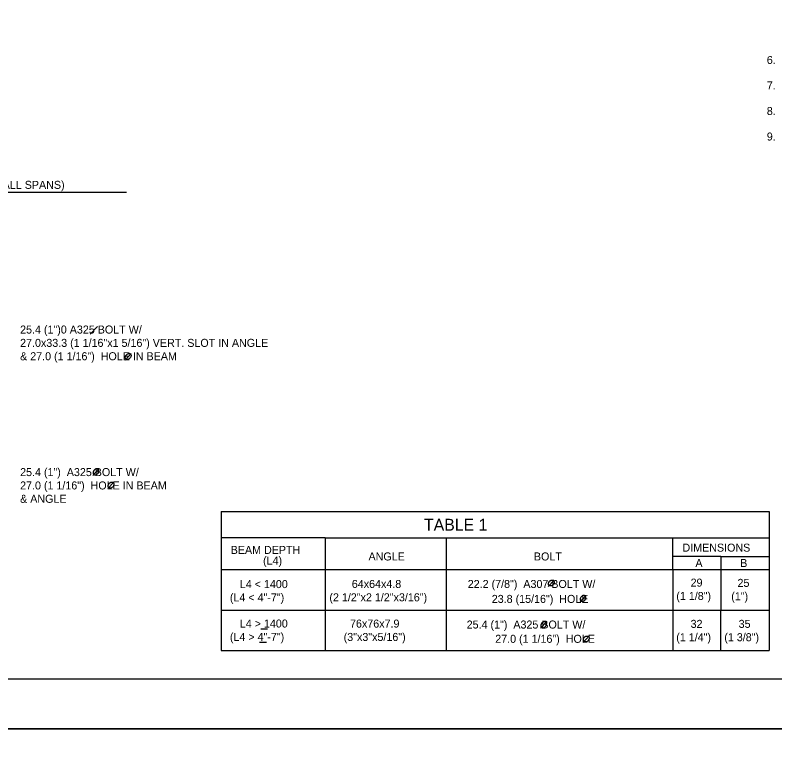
# Model space of a CAD drawing. Extents: x -13 to 81, y -176 to 0.
# Drawn here: x 47.85 to 59.23, y -22.38 to -11.31 of the extents above; entities that cross this region are included whole.
import ezdxf

# ---------------------------------------------------------------- set-up
doc = ezdxf.new("R2010")
doc.units = 0
for name, color, linetype in [('Level 1', 7, 'Continuous'), ('Level 3', 7, 'Continuous'), ('Level 4', 7, 'Continuous'), ('Level 5', 7, 'Continuous'), ('Level 63', 7, 'Continuous'), ('Level 8', 7, 'Continuous')]:
    doc.layers.add(name, color=color, linetype=linetype)

msp = doc.modelspace()

# ---------------------------------------------------------------- linework, layer by layer
at = {"layer": 'Level 1'}
msp.add_lwpolyline([(35.75, -21.25), (67.25, -21.25), (67.25, -0.75), (35.75, -0.75)], close=True, dxfattribs=at)
at = {"layer": 'Level 3'}
for p, q in [((49.087, -15.973), (48.974, -16.086)), ((51.532, -20.504), (51.635, -20.504)), ((51.512, -20.702), (51.616, -20.702))]:
    msp.add_line(p, q, dxfattribs=at)
at = {"layer": 'Level 4'}
for p, q in [((49.499, -16.475), (49.588, -16.377)), ((49.017, -18.203), (49.107, -18.104)), ((49.241, -18.402), (49.331, -18.304)), ((55.84, -19.869), (55.929, -19.771)), ((56.315, -20.1), (56.404, -20.002)), ((55.725, -20.494), (55.814, -20.396)), ((56.363, -20.707), (56.452, -20.609))]:
    msp.add_line(p, q, dxfattribs=at)
for points in [[(49.579, -16.386), (49.572, -16.381), (49.565, -16.379), (49.556, -16.378), (49.551, -16.378), (49.543, -16.38), (49.535, -16.384), (49.529, -16.387), (49.519, -16.395), (49.51, -16.406), (49.505, -16.416), (49.502, -16.425), (49.501, -16.434), (49.502, -16.441), (49.506, -16.452), (49.51, -16.457), (49.517, -16.463), (49.529, -16.466), (49.542, -16.466), (49.559, -16.458), (49.571, -16.447), (49.58, -16.435), (49.586, -16.421), (49.588, -16.407), (49.586, -16.397), (49.579, -16.386)], [(49.097, -18.114), (49.09, -18.109), (49.083, -18.107), (49.075, -18.106), (49.069, -18.106), (49.061, -18.108), (49.053, -18.112), (49.048, -18.115), (49.037, -18.123), (49.029, -18.134), (49.024, -18.144), (49.021, -18.153), (49.02, -18.162), (49.021, -18.169), (49.024, -18.18), (49.028, -18.185), (49.036, -18.191), (49.047, -18.194), (49.061, -18.194), (49.077, -18.186), (49.09, -18.175), (49.099, -18.163), (49.105, -18.149), (49.107, -18.135), (49.104, -18.125), (49.098, -18.114)], [(49.322, -18.313), (49.314, -18.308), (49.307, -18.306), (49.299, -18.305), (49.294, -18.305), (49.285, -18.307), (49.277, -18.311), (49.272, -18.314), (49.261, -18.323), (49.253, -18.333), (49.248, -18.343), (49.245, -18.353), (49.244, -18.361), (49.245, -18.369), (49.249, -18.379), (49.252, -18.385), (49.26, -18.391), (49.272, -18.393), (49.285, -18.393), (49.302, -18.385), (49.314, -18.375), (49.323, -18.362), (49.329, -18.349), (49.331, -18.334), (49.328, -18.325), (49.322, -18.313)], [(55.92, -19.78), (55.913, -19.775), (55.906, -19.773), (55.897, -19.772), (55.892, -19.772), (55.884, -19.774), (55.876, -19.778), (55.87, -19.781), (55.86, -19.79), (55.851, -19.8), (55.846, -19.81), (55.843, -19.82), (55.842, -19.828), (55.843, -19.836), (55.847, -19.846), (55.851, -19.852), (55.858, -19.858), (55.87, -19.86), (55.883, -19.86), (55.9, -19.852), (55.912, -19.842), (55.921, -19.829), (55.927, -19.816), (55.929, -19.801), (55.927, -19.792), (55.92, -19.78)], [(56.395, -20.011), (56.388, -20.006), (56.381, -20.004), (56.372, -20.003), (56.367, -20.003), (56.359, -20.005), (56.351, -20.009), (56.345, -20.012), (56.335, -20.02), (56.326, -20.031), (56.321, -20.041), (56.319, -20.05), (56.318, -20.059), (56.319, -20.066), (56.322, -20.077), (56.326, -20.082), (56.334, -20.088), (56.345, -20.091), (56.358, -20.091), (56.375, -20.083), (56.387, -20.073), (56.396, -20.06), (56.402, -20.047), (56.404, -20.032), (56.402, -20.023), (56.396, -20.011)], [(55.805, -20.406), (55.798, -20.401), (55.791, -20.399), (55.782, -20.398), (55.777, -20.398), (55.769, -20.4), (55.761, -20.403), (55.755, -20.406), (55.745, -20.415), (55.736, -20.426), (55.731, -20.436), (55.728, -20.445), (55.728, -20.454), (55.728, -20.461), (55.732, -20.472), (55.736, -20.477), (55.744, -20.483), (55.755, -20.486), (55.768, -20.485), (55.785, -20.478), (55.797, -20.467), (55.806, -20.454), (55.812, -20.441), (55.814, -20.427), (55.812, -20.417), (55.806, -20.406)], [(56.443, -20.619), (56.436, -20.613), (56.429, -20.611), (56.42, -20.611), (56.415, -20.611), (56.407, -20.613), (56.399, -20.616), (56.393, -20.619), (56.383, -20.628), (56.374, -20.639), (56.369, -20.649), (56.366, -20.658), (56.365, -20.666), (56.366, -20.674), (56.37, -20.684), (56.374, -20.69), (56.381, -20.696), (56.393, -20.698), (56.406, -20.698), (56.423, -20.69), (56.435, -20.68), (56.444, -20.667), (56.45, -20.654), (56.452, -20.639), (56.45, -20.63), (56.443, -20.619)]]:
    msp.add_spline(points, degree=3, dxfattribs=at)
at = {"layer": 'Level 5'}
for p, q in [((50.937, -18.745), (50.937, -20.829)), ((50.937, -18.745), (59.149, -18.745)), ((59.149, -18.745), (59.149, -19.418)), ((52.496, -19.139), (50.937, -19.139)), ((52.496, -19.139), (52.496, -20.829)), ((52.496, -19.139), (54.312, -19.139)), ((54.312, -19.139), (54.312, -20.829)), ((54.312, -19.139), (59.149, -19.139)), ((57.704, -19.615), (57.704, -19.139)), ((58.426, -19.418), (57.704, -19.418)), ((58.426, -19.418), (59.149, -19.418)), ((58.426, -19.418), (58.426, -19.615)), ((59.149, -19.418), (59.149, -20.829)), ((50.937, -19.615), (52.496, -19.615)), ((52.496, -19.615), (54.312, -19.615)), ((54.312, -19.615), (57.704, -19.615)), ((57.704, -19.615), (57.704, -20.829)), ((57.704, -19.615), (58.426, -19.615)), ((58.426, -19.615), (59.149, -19.615)), ((58.426, -19.615), (58.426, -20.221)), ((50.937, -20.221), (52.496, -20.221)), ((52.496, -20.221), (54.312, -20.221)), ((54.312, -20.221), (57.704, -20.221)), ((57.704, -20.221), (58.426, -20.221)), ((58.426, -20.221), (59.149, -20.221)), ((58.426, -20.829), (58.426, -20.221)), ((50.937, -20.829), (52.496, -20.829)), ((52.496, -20.829), (54.312, -20.829)), ((54.312, -20.829), (57.704, -20.829)), ((57.704, -20.829), (59.149, -20.829))]:
    msp.add_line(p, q, dxfattribs=at)
at = {"layer": 'Level 63'}
for points in [[(34, -22), (68, -22), (68, 0), (34, 0)], [(34, -44), (68, -44), (68, -22), (34, -22)]]:
    msp.add_lwpolyline(points, close=True, dxfattribs=at)
at = {"layer": 'Level 8'}
msp.add_line((45.692, -13.961), (49.52, -13.961), dxfattribs=at)

# ---------------------------------------------------------------- texts
at = {"layer": 'Level 3'}
for s, height, p in [('6.', 0.12, (59.114, -12.039)), ('7.', 0.12, (59.114, -12.421)), ('8.', 0.12, (59.114, -12.804)), ('9.', 0.12, (59.114, -13.186)), ('79 (3 1/8") (FIXED FOR ALL SPANS)', 0.12, (45.923, -13.91)), ('25.4 (1")0 A325 BOLT W/', 0.12, (47.926, -16.078)), ('27.0x33.3 (1 1/16"x1 5/16") VERT. SLOT IN ANGLE', 0.12, (47.926, -16.278)), ('& 27.0 (1 1/16")  HOLE IN BEAM', 0.12, (47.926, -16.478)), ('25.4 (1")  A325 BOLT W/', 0.12, (47.926, -18.214)), ('27.0 (1 1/16")  HOLE IN BEAM', 0.12, (47.926, -18.414)), ('& ANGLE', 0.12, (47.926, -18.614)), ('TABLE 1', 0.1772, (53.978, -19.031)), ('DIMENSIONS', 0.12, (57.85, -19.346)), ('BEAM DEPTH', 0.12, (51.081, -19.38)), ('(L4)', 0.12, (51.566, -19.54)), ('ANGLE', 0.12, (53.146, -19.478)), ('BOLT', 0.12, (55.624, -19.478)), ('A', 0.12, (58.044, -19.576)), ('B', 0.12, (58.715, -19.576)), ('L4 < 1400', 0.12, (51.218, -19.892)), ('64x64x4.8', 0.12, (52.896, -19.89)), ('22.2 (7/8")  A307 BOLT W/', 0.12, (54.633, -19.89)), ('29', 0.12, (57.972, -19.87)), ('25', 0.12, (58.675, -19.874)), ('(L4 < 4"-7")', 0.12, (51.069, -20.092)), ('(2 1/2"x2 1/2"x3/16")', 0.12, (52.56, -20.09)), ('23.8 (15/16")  HOLE', 0.12, (54.993, -20.114)), ('(1 1/8")', 0.12, (57.758, -20.07)), ('(1")', 0.12, (58.581, -20.074)), ('L4 > 1400', 0.12, (51.218, -20.483)), ('76x76x7.9', 0.12, (52.869, -20.484)), ('25.4 (1")  A325 BOLT W/', 0.12, (54.617, -20.498)), ('32', 0.12, (57.972, -20.488)), ('35', 0.12, (58.692, -20.488)), ('(L4 > 4"-7")', 0.12, (51.069, -20.683)), ('(3"x3"x5/16")', 0.12, (52.774, -20.684)), ('27.0 (1 1/16")  HOLE', 0.12, (55.045, -20.712)), ('(1 1/4")', 0.12, (57.757, -20.688)), ('(1 3/8")', 0.12, (58.477, -20.688))]:
    msp.add_text(s, height=height, dxfattribs=at).set_placement(p)

doc.saveas('drawing.dxf')
